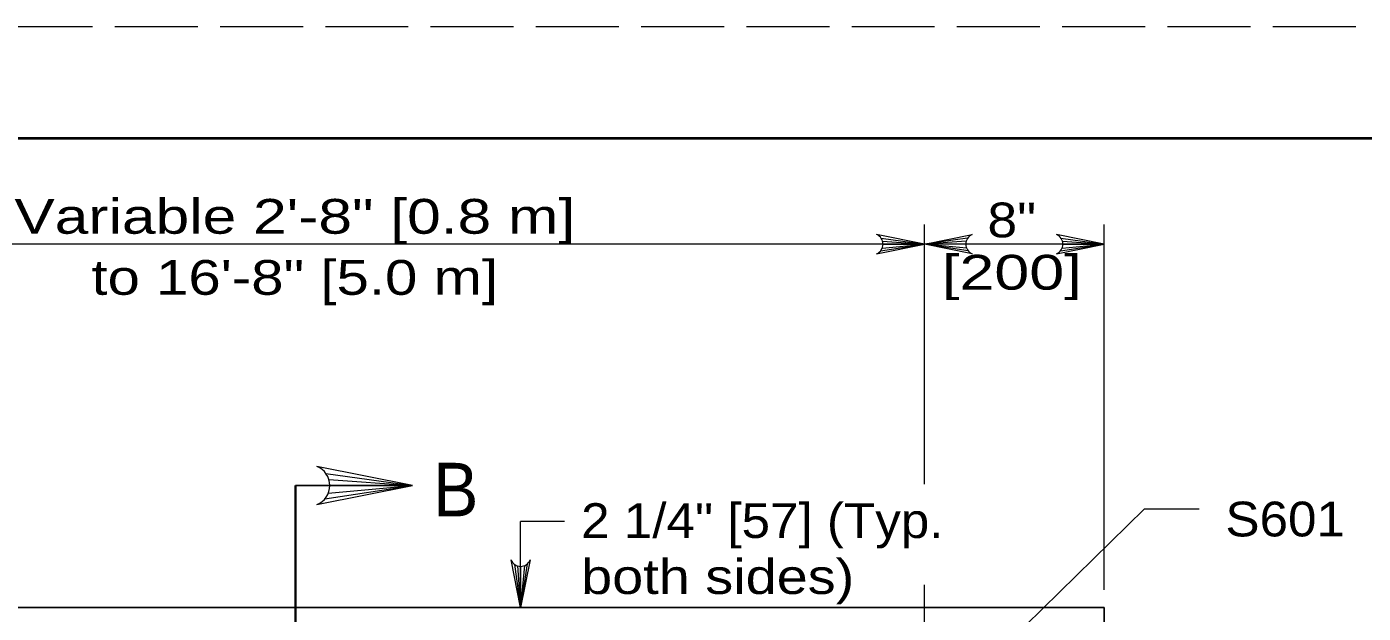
# Model space of a CAD drawing. Extents: x 758.3 to 792.3, y 849.7 to 893.7.
# Drawn here: x 771.26 to 777.25, y 891.06 to 893.69 of the extents above; entities that cross this region are included whole.
import ezdxf
from ezdxf.enums import TextEntityAlignment as Align

# ---------------------------------------------------------------- set-up
doc = ezdxf.new("R2010")
doc.units = 0
doc.header["$LTSCALE"] = 0.062
doc.linetypes.add('LONG_DASHED', pattern=[7.5, 6, -1.5])
doc.layers.add('1', color=7, linetype='Continuous', lineweight=13)

msp = doc.modelspace()

# ---------------------------------------------------------------- linework, layer by layer
at = {"layer": '1', "lineweight": 25}
for p, q in [((760.3205, 893.18817), (791.8205, 893.18817)), ((772.98675, 891.62983), (772.46325, 891.62983)), ((776.08867, 891.08192), (764.9015, 891.08192)), ((776.08867, 887.05092), (776.08867, 891.08192))]:
    msp.add_line(p, q, dxfattribs=at)
at = {"layer": '1'}
for p, q in [((775.28242, 891.63625), (775.28242, 892.80025)), ((776.08867, 891.1615), (776.08867, 892.80025)), ((774.59692, 892.71267), (769.73917, 892.71267)), ((775.28242, 892.71267), (774.59692, 892.71267)), ((775.08625, 892.68275), (775.28242, 892.71267)), ((775.0885, 892.73983), (775.28242, 892.71267)), ((775.09367, 892.69525), (775.28242, 892.71267)), ((775.09508, 892.72642), (775.28242, 892.71267)), ((775.09708, 892.71267), (775.28242, 892.71267)), ((775.47633, 892.73983), (775.28242, 892.71267)), ((775.46975, 892.72642), (775.28242, 892.71267)), ((776.08867, 892.71267), (775.28242, 892.71267)), ((775.46775, 892.71267), (775.28242, 892.71267)), ((775.47117, 892.69525), (775.28242, 892.71267)), ((775.47858, 892.68275), (775.28242, 892.71267)), ((776.08867, 892.71267), (775.78758, 892.71267)), ((775.8925, 892.68275), (776.08867, 892.71267)), ((775.89483, 892.73983), (776.08867, 892.71267)), ((775.89992, 892.69525), (776.08867, 892.71267)), ((775.90142, 892.72642), (776.08867, 892.71267)), ((775.90333, 892.71267), (776.08867, 892.71267)), ((772.599, 891.68408), (772.98675, 891.62983)), ((772.59442, 891.56983), (772.98675, 891.62983)), ((772.60925, 891.595), (772.98675, 891.62983)), ((772.61208, 891.65725), (772.98675, 891.62983)), ((772.61608, 891.62983), (772.98675, 891.62983)), ((773.47208, 891.08192), (773.47208, 891.46883)), ((773.66808, 891.46883), (773.47208, 891.46883)), ((773.445, 891.27583), (773.47208, 891.08192)), ((773.45842, 891.26925), (773.47208, 891.08192)), ((773.50208, 891.27808), (773.47208, 891.08192)), ((773.4895, 891.27067), (773.47208, 891.08192)), ((773.47208, 891.26725), (773.47208, 891.08192)), ((775.28242, 890.361), (775.28242, 891.18492))]:
    msp.add_line(p, q, dxfattribs=at)
at = {"layer": '1', "lineweight": 35}
msp.add_line((772.46325, 891.62983), (772.46325, 890.33417), dxfattribs=at)
at = {"layer": '1', "linetype": 'LONG_DASHED'}
msp.add_lwpolyline([(758.3205, 871.68817), (792.3205, 871.68817), (792.3205, 893.68817), (758.3205, 893.68817)], close=True, dxfattribs=at)
at = {"layer": '1', "lineweight": 40}
msp.add_lwpolyline([(760.3205, 893.18817), (791.8205, 893.18817), (791.8205, 872.18817), (760.3205, 872.18817)], close=True, dxfattribs=at)
at = {"layer": '1'}
for points in [[(775.06825, 892.66983), (775.28242, 892.71267), (775.06825, 892.7555)], [(775.49658, 892.66983), (775.28242, 892.71267), (775.49658, 892.7555)], [(775.8745, 892.66983), (776.08867, 892.71267), (775.8745, 892.7555)], [(772.55842, 891.54417), (772.98675, 891.62983), (772.55842, 891.7155)], [(775.35458, 890.62842), (776.26983, 891.52542), (776.51467, 891.52542)], [(773.51492, 891.29608), (773.47208, 891.08192), (773.42925, 891.29608)]]:
    msp.add_lwpolyline(points, dxfattribs=at)
for centre, radius, start, end in [((775.05095, 892.71275), 0.04623, 292.08605, 67.91218), ((775.51388, 892.71275), 0.04623, 112.08782, 247.91395), ((775.85724, 892.71275), 0.04623, 292.08605, 67.91218), ((772.52383, 891.62992), 0.09245, 292.08605, 67.91218), ((773.47205, 891.31338), 0.04623, 202.08782, 337.91395)]:
    msp.add_arc(centre, radius, start, end, dxfattribs=at)

# ---------------------------------------------------------------- texts
for s, width, p in [('Variable 2\'-8" [0.8 m]', 1.3, (772.45933, 892.75942)), ('8"', 1.15, (775.67437, 892.74325)), ('to 16\'-8" [5.0 m]', 1.25, (772.45933, 892.48542)), ('[200]', 1.35, (775.67446, 892.50858))]:
    msp.add_text(s, height=0.156, dxfattribs=dict(at, width=width)).set_placement(p, align=Align.CENTER)
for s, height, width, p in [('B', 0.24, 0.95, (773.07958, 891.49167)), ('2 1/4" [57] (Typ.', 0.156, 1.1, (773.74342, 891.39442)), ('S601', 0.156, 1.1, (776.63233, 891.4015)), ('both sides)', 0.156, 1.2, (773.74342, 891.14325))]:
    msp.add_text(s, height=height, dxfattribs=dict(at, width=width)).set_placement(p)

doc.saveas('drawing.dxf')
